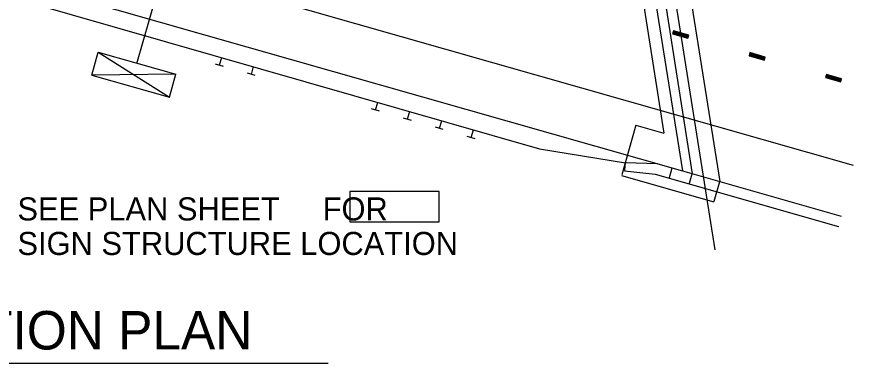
# Model space of a CAD drawing. Extents: x 640117 to 642655, y 297247 to 298435.
# Drawn here: x 641580.9 to 641689.6, y 297989.9 to 298034.9 of the extents above; entities that cross this region are included whole.
import ezdxf

# ---------------------------------------------------------------- set-up
doc = ezdxf.new("R2010")
doc.units = 0
for name, color, linetype in [('2', 7, 'Continuous'), ('26', 7, 'Continuous'), ('27', 7, 'Continuous'), ('43', 7, 'Continuous'), ('48', 7, 'Continuous'), ('50', 7, 'Continuous'), ('51', 7, 'Continuous')]:
    doc.layers.add(name, color=color, linetype=linetype)

msp = doc.modelspace()

# ---------------------------------------------------------------- linework, layer by layer
at = {"layer": '2'}
msp.add_line((641558.32, 297989.9), (641621.37, 297989.9), dxfattribs=at)
msp.add_lwpolyline([(641624.19, 298008.28), (641635.81, 298008.28), (641635.81, 298012.22), (641624.19, 298012.22)], close=True, dxfattribs=at)
at = {"layer": '26'}
for p, q in [((641502.27, 298069.03), (641689.65, 298015.64)), ((641500.14, 298062.57), (641667.43, 298014.9))]:
    msp.add_line(p, q, dxfattribs=at)
at = {"layer": '27'}
for p, q in [((641607.77, 298028.48), (641606.73, 298028.78)), ((641607.25, 298028.63), (641607.55, 298029.67)), ((641611.4, 298027.44), (641611.69, 298028.48)), ((641611.91, 298027.29), (641610.88, 298027.59)), ((641627.55, 298022.8), (641627.84, 298023.84)), ((641628.06, 298022.65), (641627.03, 298022.95)), ((641631.69, 298021.61), (641631.99, 298022.65)), ((641632.21, 298021.46), (641631.17, 298021.76)), ((641635.84, 298020.42), (641636.14, 298021.45)), ((641636.35, 298020.27), (641635.32, 298020.57)), ((641639.97, 298019.23), (641640.27, 298020.26)), ((641640.49, 298019.08), (641639.46, 298019.38))]:
    msp.add_line(p, q, dxfattribs=at)
msp.add_lwpolyline([(641563.87, 298042.17), (641648.86, 298017.76), (641660.03, 298015.97)], dxfattribs=at)
at = {"layer": '43'}
for p, q in [((641596.52, 298028.88), (641616.52, 298099.06)), ((641590.64, 298027.35), (641591.49, 298030.33)), ((641591.49, 298030.33), (641601.57, 298027.46)), ((641591.49, 298030.33), (641600.73, 298024.48)), ((641601.57, 298027.46), (641590.64, 298027.35)), ((641590.64, 298027.35), (641600.73, 298024.48)), ((641600.73, 298024.48), (641601.58, 298027.46))]:
    msp.add_line(p, q, dxfattribs=at)
at = {"layer": '48'}
for points in [[(641666.16, 298032.71), (641668.15, 298032.14), (641668.27, 298032.53), (641666.28, 298033.1)], [(641666.22, 298032.73), (641668.12, 298032.19), (641668.21, 298032.5), (641666.31, 298033.05)], [(641666.28, 298032.76), (641668.09, 298032.25), (641668.16, 298032.47), (641666.34, 298032.99)], [(641666.32, 298032.79), (641668.07, 298032.29), (641668.11, 298032.45), (641666.37, 298032.94)], [(641666.36, 298032.81), (641668.04, 298032.34), (641668.07, 298032.42), (641666.38, 298032.9)], [(641666.4, 298032.83), (641668.02, 298032.37), (641668.03, 298032.4), (641666.41, 298032.86)], [(641676.1, 298029.87), (641678.09, 298029.3), (641678.2, 298029.7), (641676.22, 298030.27)], [(641676.16, 298029.9), (641678.06, 298029.36), (641678.15, 298029.67), (641676.24, 298030.21)], [(641676.22, 298029.93), (641678.03, 298029.41), (641678.09, 298029.64), (641676.28, 298030.16)], [(641676.26, 298029.96), (641678, 298029.46), (641678.05, 298029.61), (641676.3, 298030.1)], [(641676.3, 298029.98), (641677.98, 298029.5), (641678, 298029.59), (641676.33, 298030.07)], [(641676.34, 298030), (641677.96, 298029.54), (641677.97, 298029.58), (641676.35, 298030.04)], [(641686.04, 298027.04), (641688.03, 298026.47), (641688.14, 298026.87), (641686.15, 298027.44)], [(641686.1, 298027.07), (641688, 298026.53), (641688.09, 298026.84), (641686.19, 298027.38)], [(641686.15, 298027.1), (641687.96, 298026.59), (641688.03, 298026.81), (641686.22, 298027.33)], [(641686.2, 298027.12), (641687.94, 298026.63), (641687.98, 298026.78), (641686.24, 298027.28)], [(641686.24, 298027.15), (641687.92, 298026.67), (641687.94, 298026.76), (641686.27, 298027.24)], [(641686.28, 298027.17), (641687.9, 298026.7), (641687.91, 298026.74), (641686.29, 298027.2)]]:
    msp.add_lwpolyline(points, close=True, dxfattribs=at)
at = {"layer": '50'}
msp.add_line((641657.68, 298093.03), (641671.65, 298004.62), dxfattribs=at)
at = {"layer": '51'}
for p, q in [((641661.3, 298083.04), (641672.28, 298013.54)), ((641656.91, 298081.45), (641667.43, 298014.9)), ((641658.19, 298081.09), (641668.71, 298014.54)), ((641655.91, 298077.51), (641665.03, 298019.81)), ((641661.39, 298020.84), (641659.55, 298014.39)), ((641661.39, 298020.84), (641665.03, 298019.81)), ((641660, 298015.98), (641659.9, 298014.97)), ((641664.18, 298015.83), (641660.03, 298015.97)), ((641659.89, 298014.89), (641663.91, 298014.48)), ((641665.75, 298014.03), (641666.11, 298015.28)), ((641667.43, 298014.9), (641688.07, 298009.02)), ((641659.52, 298014.31), (641671.53, 298010.89)), ((641663.9, 298014.48), (641687.73, 298007.69)), ((641668.35, 298013.29), (641668.71, 298014.54)), ((641671.56, 298010.97), (641672.28, 298013.52))]:
    msp.add_line(p, q, dxfattribs=at)

# ---------------------------------------------------------------- texts
at = {"layer": '2'}
for s, height, p in [('SEE PLAN SHEET     FOR', 2.9999, (641580.98, 298008.46)), ('SIGN STRUCTURE LOCATION', 2.9999, (641580.98, 298003.97)), ('LOCATION PLAN', 4.9956, (641558.07, 297991.69))]:
    msp.add_text(s, height=height, dxfattribs=at).set_placement(p)

doc.saveas('drawing.dxf')
